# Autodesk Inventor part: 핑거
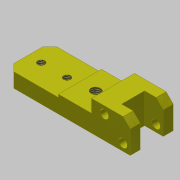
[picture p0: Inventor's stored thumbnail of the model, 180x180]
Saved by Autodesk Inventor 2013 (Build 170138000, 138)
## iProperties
Created: 2019-02
Part Number: 핑거
Material: 알루미늄 6061
Document SubType Name: Modeling
Designer: mduedu
Density: 1 g/cm^3
Author: mduedu
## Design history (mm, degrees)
sketch "스케치1"
  geometry: L1 (0, 0)-(-86, 0); L2 (-86, 0)-(-86, 21); L3 (-86, 21)-(0, 21); L4 (0, 21)-(0, 0)
  constraints: 8 end point, 2 parallel, 1 horizontal, 1 perpendicular
  dimensions: "d0" = 86 distance of L2.end L3.end; "d1" = 21 distance of L1.end L2.end
extrude "돌출1" new body sketch "스케치1" stored distance "d2" = 30; taper "d3" = 0 deg
sketch "스케치2"
  geometry: L1 (-86, 0)-(0, 0) reference; L2 (0, 0)-(0, 21) reference; L3 (0, 21)-(-86, 21) reference; L4 (-86, 21)-(-86, 0) reference; L5 (-86, 10)-(-50, 10); L6 (-50, 10)-(-50, 21); L7 (-50, 21)-(-86, 21); L8 (-86, 21)-(-86, 10); L9 (-50, 12)-(-27, 12); L10 (-27, 12)-(-27, 21); L11 (-27, 21)-(-50, 21); L12 (-50, 21)-(-50, 12); 1 further point
  constraints: 16 end point, 4 parallel, 4 point on line, 2 horizontal, 2 perpendicular
  dimensions: "d4" = 27 distance between parallel lines of L10 L2; "d5" = 12 distance between parallel lines of L1 L9; "d6" = 36 distance between parallel lines of L6 L4; "d7" = 10 distance between parallel lines of L1 L5
extrude "돌출2" cut sketch "스케치2" stored distance "d8" = 30; taper "d9" = 0 deg
chamfer "모따기1" distance "d10" = 5; stored, may be unused: second distance "d11" = 2, angle "d12" = 45 deg
sketch "스케치3"
  geometry: L1 (27, 0)-(27, 30) reference; L2 (27, 23)-(14, 23); L3 (14, 23)-(14, 7); L4 (14, 7)-(27, 7); L5 (27, 7)-(27, 23); 2 further points
  constraints: 8 end point, 2 midpoint, 2 parallel, 1 horizontal, 1 perpendicular, 1 point on line
  dimensions: "d13" = 16 distance between parallel lines of L4 L2; "d15" = 13 distance of L2.start L2.end
extrude "돌출3" cut sketch "스케치3" stored distance "d16" = 30; taper "d17" = 0 deg
sketch "스케치4"
  geometry: 3 further points
  dimensions: "d18" = 5 horizontal distance of point (-5, 5) point (0, 0); "d19" = 5 horizontal distance of point (-5, 5) point (0, 0); "d20" = 11 vertical distance of point (-18, 16) point (-5, 5); "d21" = 13 horizontal distance of point (-18, 16) point (-5, 5)
hole "구멍1" sketch "스케치4" at (-5, 5), (-18, 16) diameter "d22" = 6; stored, may be unused: countersink angle "d26" = 90 deg, drill point angle "d28" = 118 deg; dims "d23" = 6, "d24" = 4, "d25" = 2, "d27" = 8
sketch "스케치5"
  geometry: L1 (0, 0)-(0, 30) reference; 3 further points
  constraints: 2 horizontal alignment
  dimensions: "d29" = 9 distance from line of point (9, 15) L1; "d30" = 18 distance of point (27, 15) point (9, 15)
hole "구멍2" sketch "스케치5" diameter "d31" = 4.917; stored, may be unused: countersink angle "d35" = 90 deg, drill point angle "d37" = 118 deg; dims "d32" = 6, "d33" = 4, "d34" = 2, "d36" = 8
sketch "스케치6"
  geometry: 3 further points
  constraints: 1 horizontal alignment
  dimensions: "d38" = 20 distance of point (11, 15) point (-9, 15)
hole "구멍3" sketch "스케치6" at (11, 15) diameter "d39" = 6.647; stored, may be unused: countersink angle "d43" = 90 deg, drill point angle "d45" = 118 deg; dims "d40" = 6, "d41" = 4, "d42" = 2, "d44" = 8
chamfer "모따기2" distance "d46" = 5; stored, may be unused: second distance "d47" = 2, angle "d48" = 45 deg
node "솔리드1"
node "투영된 루프1"
